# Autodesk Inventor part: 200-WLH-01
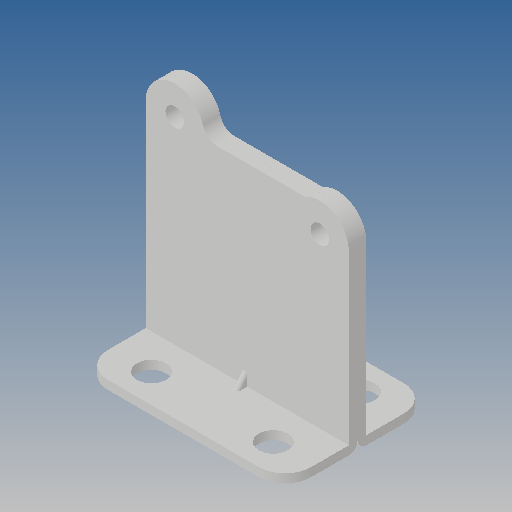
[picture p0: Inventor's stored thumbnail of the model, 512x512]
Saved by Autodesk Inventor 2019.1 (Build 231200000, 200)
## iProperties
Created: 2011-05
Part Number: 200-WLH-01
Material: Ogólny
Document SubType Name: Modeling
Designer: CADENGINEERING4
Density: 1 g/cm^3
Appearance: Domyślna
Author: CADENGINEERING4
Revision Number: ÈÎºÎ
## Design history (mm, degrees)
feature "ÇÐ³ý-À­Éì1"
feature "¾µÏò4"
node "Bryła1"
node "Bryła2"
